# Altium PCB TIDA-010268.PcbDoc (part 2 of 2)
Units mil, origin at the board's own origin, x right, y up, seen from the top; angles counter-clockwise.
Board outline 3937.2 x 2362.29 mil, 2 copper layers (Top Layer, Bottom Layer), stack 62 mil thick; 154 components, 100 nets, 480 pads, 602 vias.
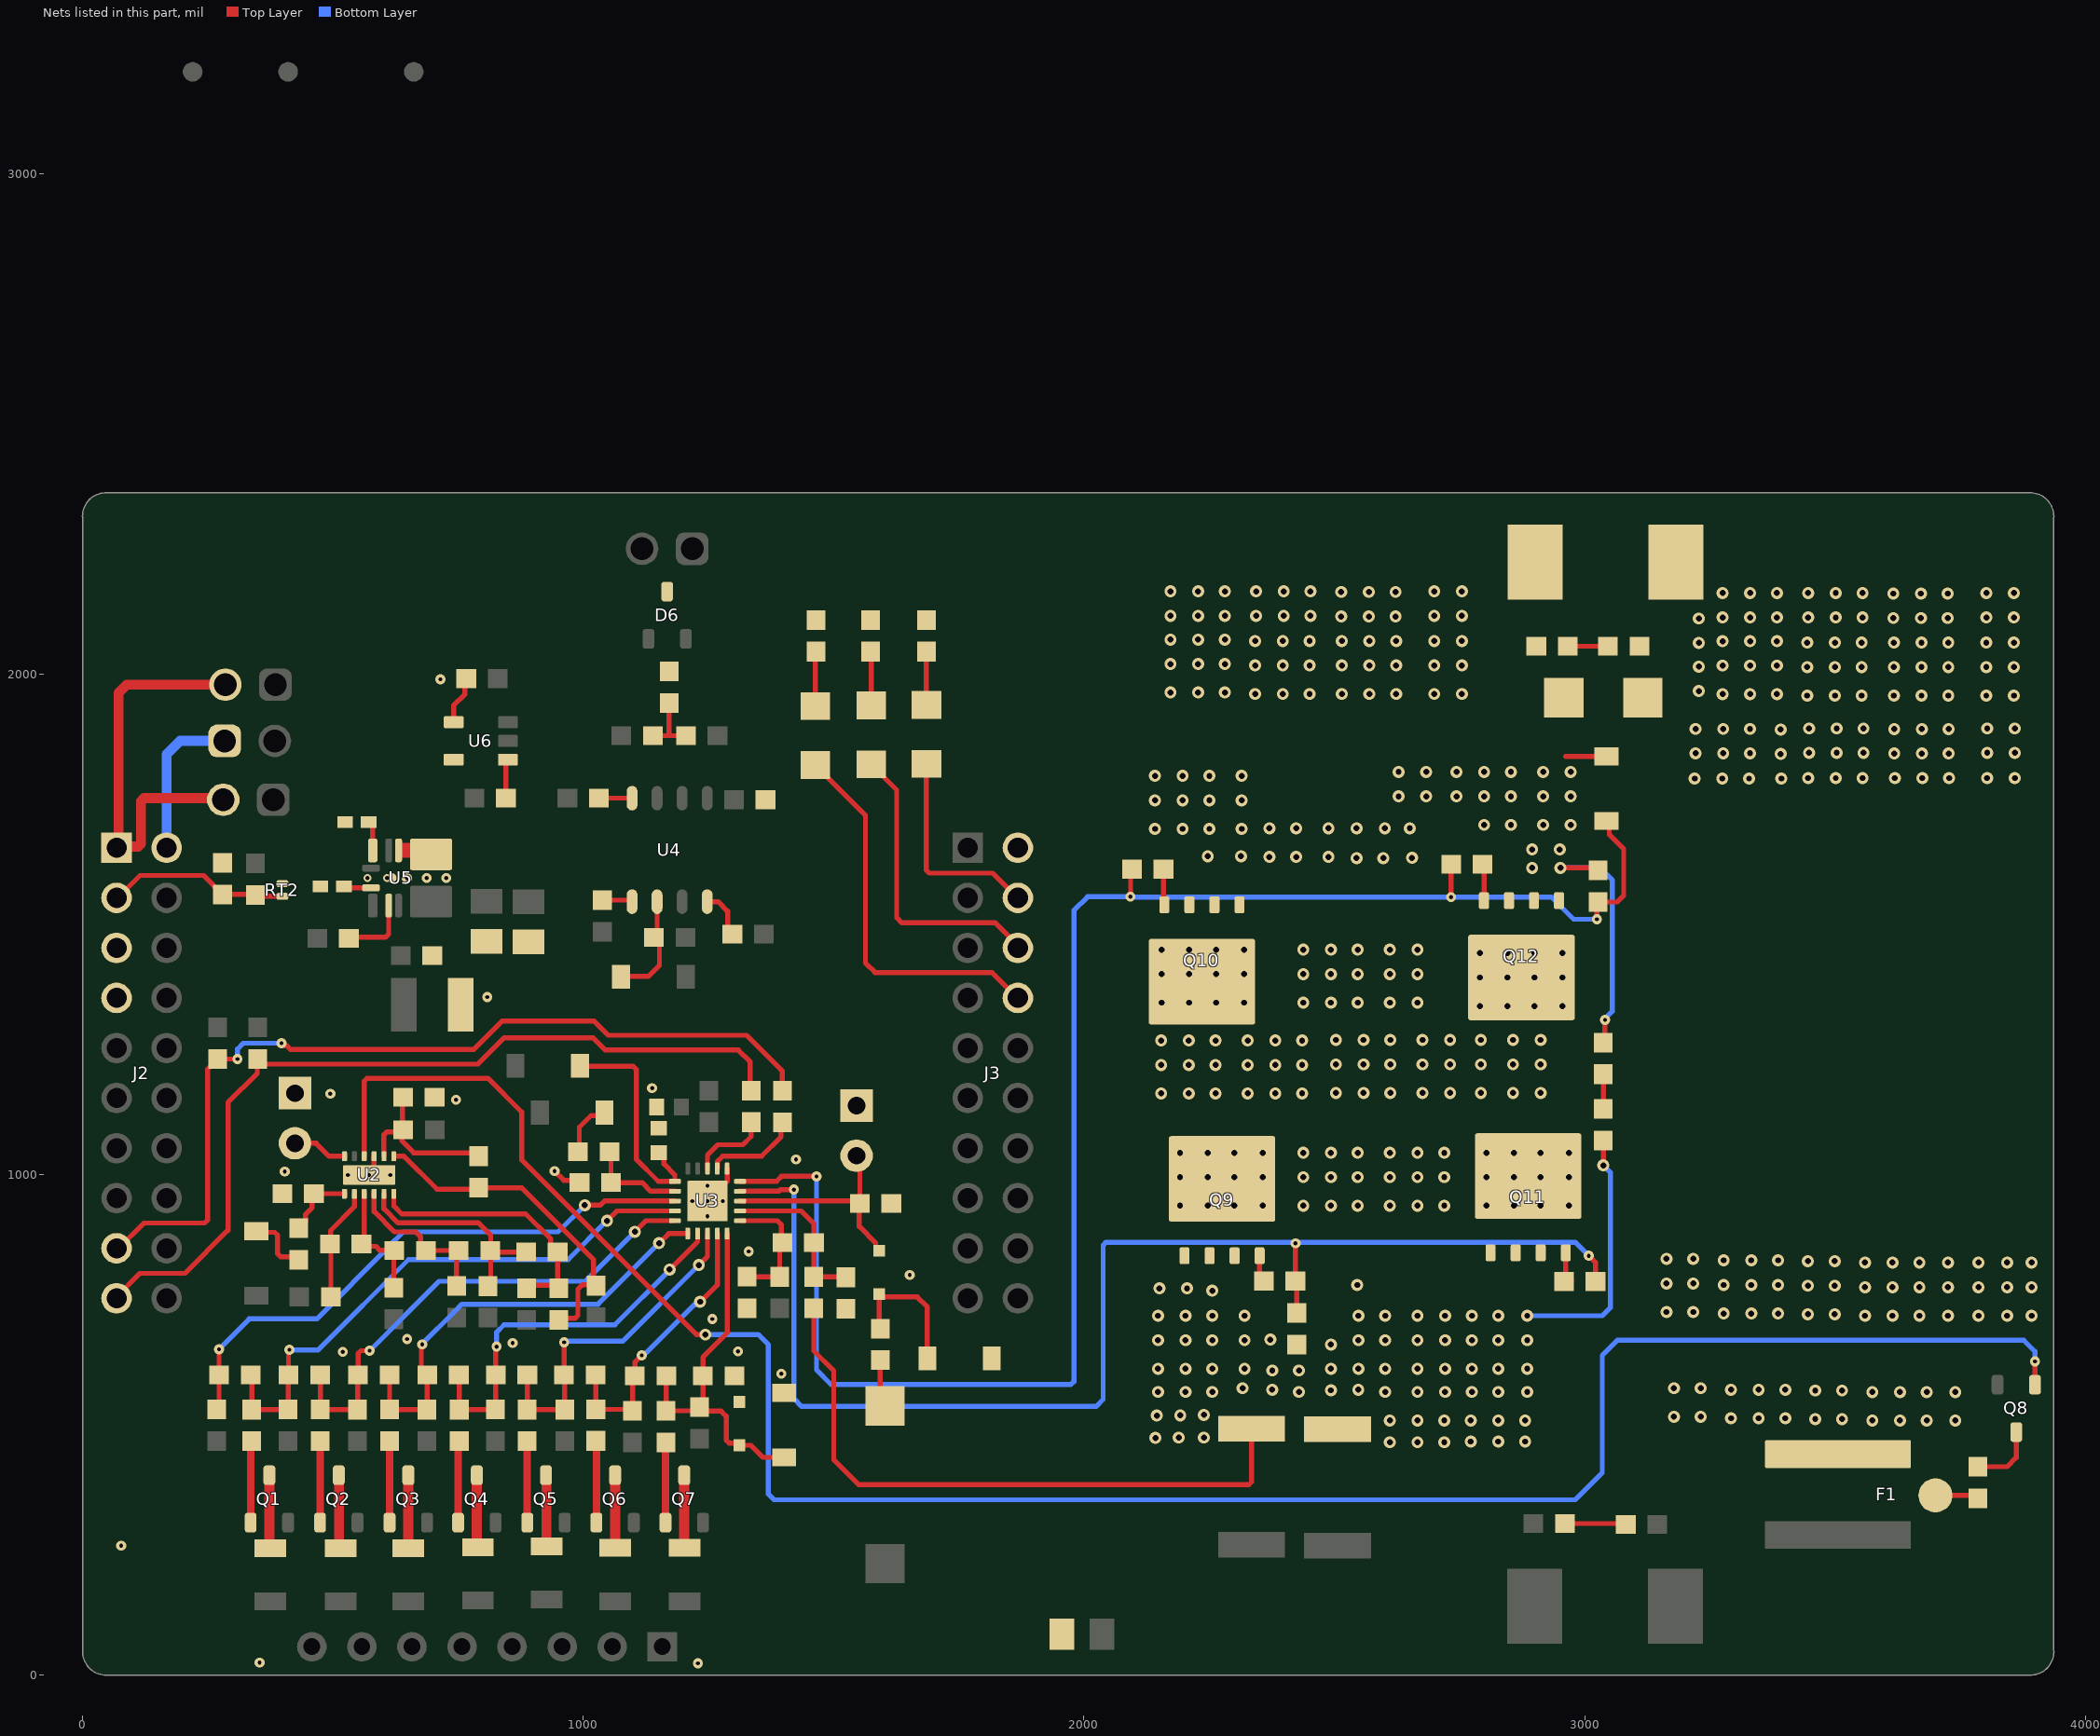
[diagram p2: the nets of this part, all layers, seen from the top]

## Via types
v1: diameter 24, hole 12, Top Layer to Bottom Layer, 526 vias
v2: diameter 20, hole 8, Top Layer to Bottom Layer, tented both sides, 55 vias
v3: diameter 19.68, hole 7.87, Top Layer to Bottom Layer, tented both sides, 8 vias
v4: diameter 19.68, hole 7.87, Top Layer to Bottom Layer, 8 vias
v5: diameter 15.75, hole 7.87, Top Layer to Bottom Layer, tented both sides, 2 vias
v6: diameter 13.78, hole 7.87, Top Layer to Bottom Layer, tented both sides, 2 vias
v7: diameter 24, hole 12, Top Layer to Bottom Layer, tented both sides, 1 vias

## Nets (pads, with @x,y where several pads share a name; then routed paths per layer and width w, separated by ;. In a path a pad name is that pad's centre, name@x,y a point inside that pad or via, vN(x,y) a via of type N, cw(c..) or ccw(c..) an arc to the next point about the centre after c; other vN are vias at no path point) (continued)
CHG: D15.1 R56.2 R60.2 R61.2 U3.10 | length 3461.5
  Top Layer w10: U3.10@1313.14,986.63 1385.98,986.63 1395.92,996.57 v2@1465.79,996.57 ; v2(2092.78,1555.22) 2093.23,1555.67 2093.23,1605.61 R60.2@2095.62,1607.99 ; v2(2733.27,1554.57) R56.2@2733.27,1619.77 ; v2(3024.25,1510.11) 3024.25,1542.15 R61.2@3026.82,1544.72 3065.2,1544.72 3078,1557.52 3078,1650.43 3049.03,1679.4 3049.03,1701.52 D15.1@3044,1706.55
  Bottom Layer w10: v2(1465.79,996.23) 1465.79,610.24 1495.16,580.87 1974.16,580.87 1980.02,586.73 1980.02,1528.03 2007.21,1555.22 v2(2092.78,1555.22) 2093.44,1554.57 v2(2733.27,1554.57) 2933.41,1554.57 2977.87,1510.11 v2(3024.25,1510.11)
COUT: Q8.1 U2.10 | length 4413.6
  Top Layer w10: U2.10@562.67,1036.66 562.67,1186.76 568.53,1192.61 809.62,1192.61 876.92,1125.32 876.92,1029.62 1225.88,680.66 1243.71,680.66 v1(1243.89,680.48) ; Q8.1@3899.4,580.24 v2(3899.4,627.01)
  Bottom Layer w10: v1(1243.89,680.48) 1349.22,680.48 1369.69,660.01 1369.69,361.82 1380.95,350.55 2981,350.55 3035.04,404.6 3035.04,639 3065.04,669 3877,669 3899.4,646.6 v2(3899.4,627.01)
DSG: R57.2 R58.2 R59.2 U3.9 | length 2634
  Top Layer w10: U3.9@1313.14,966.95 1390.87,966.95 1394.06,970.14 v2(1420.87,970.14) ; v2(2422.5,862.64) 2422.5,793.81 R59.2@2425,791.31 ; R57.2@2425,736.53 R59.2@2425,791.31 ; R59.2@2425,793.5 R59.2@2425,791.31 ; v2(3008.12,837.98) 3021.74,824.35 R58.2@3021.74,786.51
  Bottom Layer w10: v2(1420.87,970.14) 1420.87,552.59 1436.46,537 2024.19,537 2038.2,551.02 2038.2,858.96 2044.06,864.82 2422.5,864.82 2981.27,864.82 v2(3008.12,837.98)
GND: C2.1 C3.2 C14.1 C15.2 C16.1 C17.1 C18.2 C19.2 C20.2 C21.2 C22.2 C23.2 C24.2 C25.2 C26.2 C27.2 C32.1 C34.2 C39.2 C41.1 D3.2 D4.2 D5.2 D6.3 D8.2 J3.2 NT1.1 R21.1 R25.1 R26.1 R29.1 RT1.1 RT2.1 RT3.1 U2.9 U2.13 U3.11 U3.21 U4.2 U5.10 U6.1 U6.4 U6.5 | length 577.9
  Top Layer w10: v4(572.51,999.26) 582.36,1009.1 U2.9@582.36,1036.66 ; U6.4@741.22,1903.9 741.22,1937.36 763.89,1960.03 C21.2@763.89,1993.47 ; C22.2@845.55,1752.08 845.55,1825.16 U6.1@849.49,1829.1 ; v2(942.93,1006.94) 961.25,988.62 987.93,988.62 C41.1@992.57,983.98 ; D3.2@1075.65,1395.22 1074.86,1396 1129.99,1396 1152.2,1418.22 1152.2,1474.25 1147.54,1478.92 U4.2@1147.54,1545.39 ; v4(1248.18,947.26) 1287.55,986.63 U3.11@1287.55,1012.22 ; NT1.1@1954.83,83.11 NT1.1@1956.02,81.92
  other v2: 1229.24,23.8 353.49,24.99 77.39,258.87 1395.59,602.27 519.71,646.07 1308.99,646.74 859.01,663.6 648.4,671.47 1258.03,711.55 1652.14,799.6 1330.5,846.67 403.92,1006.12 1424.89,1030.57 746.03,1149.43 494.94,1161.49 1137.56,1172.94 808.17,1354.59 714.63,1989.41
  other v3: 647.77,1592.63 687.14,1592.63 726.51,1592.63
  other v4: 1248.18,916.75 1217.66,947.26 1278.69,947.26 1248.18,977.77 530.19,999.26 614.84,999.26
  other v5: 569.03,1592.63 608.4,1592.63
LED1: D9.2 J3.4 | length 436.9
  Top Layer w10: D9.2@1685.38,1839.24 1685.38,1608.3 1691.24,1602.44 1817.56,1602.44 J3.4@1868,1552
LED2: D10.2 J3.6 | length 597.8
  Top Layer w10: D10.2@1575.11,1819.31 1625.91,1768.51 1625.91,1513.59 1636.55,1502.95 1822.99,1502.95 1868,1457.94 J3.6@1868,1452
LED3: D11.2 J3.8 | length 770.5
  Top Layer w10: D11.2@1463.38,1818.24 1563.66,1717.96 1563.66,1423 1582.92,1403.74 1816.26,1403.74 J3.8@1868,1352
NetC2_2: C2.2 R6.2 U2.1 | length 142.6
  Top Layer w10: R6.2@431.84,893.04 445.54,906.74 445.54,920.99 458.57,934.02 458.57,958.46 C2.2@461.96,961.86 U2.1@523.3,961.86
NetC3_1: C3.1 J2.3 R22.1 RT2.2 | length 366.2
  Top Layer w10: J2.3@69.18,1552 114.87,1597.68 241.66,1597.68 C3.1@279.6,1559.74 344.68,1559.74 R22.1@345.55,1558.87 348.5,1555.92 RT2.2@399.19,1555.92
NetC4_1: C4.1 R34.2 U2.2 | length 226.5
  Top Layer w10: C4.1@495.59,850.78 495.59,888.42 542.99,935.82 U2.2@542.99,961.86 ; R34.2@495.96,755.77 C4.1@495.96,849.57 ; R34.2@507.08,756.8 R34.2@508.45,755.43
NetC4_2: C4.2 C5.1 R40.2 U2.3 | length 253.5
  Top Layer w10: C4.2@557.15,861.74 C4.2@562.67,861.74 ; C4.2@561.88,861.74 566.83,856.79 585.98,856.79 594.11,848.66 622.6,848.66 C5.1@622.94,848.32 621.79,847.17 R40.2@621.79,774.18 ; C4.2@562.67,855.06 C4.2@562.67,861.74 ; U2.3@562.67,961.86 C4.2@562.67,861.74
NetC5_2: C5.2 C7.1 R44.2 U2.4 | length 311.8
  Top Layer w10: U2.4@582.36,961.86 582.36,926.39 623.02,885.73 665.39,885.73 674.96,876.16 674.96,859.28 C5.2@685.93,848.32 C7.1@751.17,848.32 ; R44.2@746.67,776.92 R44.2@747.13,777.37 747.13,834.65 C7.1@752.37,839.89
NetC7_2: C7.2 C10.1 R46.2 U2.5 | length 442.2
  Top Layer w10: U2.5@602.04,961.86 602.04,931.98 630.42,903.61 790.92,903.61 808.79,885.73 815.36,879.17 C7.2@815.36,839.89 ; R46.2@809.5,777.13 815.36,782.99 C7.2@815.36,839.89 ; C10.1@885.74,845.41 882.79,845.41 820.87,845.41 C7.2@815.36,839.89
NetC10_2: C10.2 C28.1 R47.2 U2.6 | length 538.9
  Top Layer w10: U2.6@621.73,961.86 621.73,937.58 637.82,921.48 884.94,921.48 935.08,871.35 935.08,859.07 C10.2@948.73,845.41 948.73,774.91 C28.1@950.88,772.76 ; R47.2@875.94,787.45 881.64,781.74 R47.2@895.25,781.74 ; R47.2@902.24,778.01 903.54,779.31 C28.1@948.73,779.31
NetC19_1: C19.1 R35.1 R38.2 | length 131.1
  Top Layer w10: R35.1@1139.19,1877.02 1171.52,1877.02 ; C19.1@1171.52,1942.28 1171.52,1877.02 ; R38.2@1205.02,1877.02 1171.52,1877.02
NetC24_1: C24.1 U5.8 | length 59.6
  Top Layer w10: C24.1@571.62,1704 572.84,1704 579.65,1697.19 U5.8@579.65,1648.44
NetC28_2: C28.2 C38.1 R48.2 U2.7 | length 651.2
  Top Layer w10: U2.7@621.73,1036.66 642.14,1036.66 707.96,970.85 C38.1@790.97,970.85 ; C38.1@790.97,973.8 876.94,973.8 1020.69,830.04 1020.69,783.42 R48.2@1025.83,778.28 ; C28.2@964.43,715.29 964.43,712.93 964.58,712.78 983.48,712.78 989.33,718.64 989.33,771.2 997.99,779.85 1014.36,779.85 R48.2@1014.83,780.33
NetC29_2: C29.2 C31.1 | length 80
  Top Layer w10: C31.1@2966.55,2055.52 C29.2@3046.5,2055.52
NetC30_2: C30.2 C35.1 | length 122.6
  Top Layer w10: C35.1@2960.5,303 3080.11,303 C30.2@3082.24,300.87
NetC36_1: C36.1 Q9.1 Q9.2 Q9.3 Q11.1 Q11.2 Q11.3 R55.2 R57.1 R62.2 R63.2 | length 1795.4
  Top Layer w10: R55.2@1460.46,732.81 1460.46,647.9 1500.45,607.91 1500.45,430.55 1550.53,380.47 2328.87,380.47 2334.73,386.33 R62.2@2334.73,492.87 ; v1(3037.34,1018.49) C36.1@3037.34,1068.37
  Bottom Layer w10: v1(2885.26,718.08) 3035.04,718.08 3051.27,734.31 3051.27,1004.55 v1(3037.34,1018.49)
  other v1: 2611,465.5 2666.14,465.5 2719.63,465.5 2772.4,466.86 2827.54,466.86 2881.03,466.86 2142.74,474.04 2189.45,474.64 2239.58,474.64 2611,508.81 2666.14,508.81 2719.63,508.81 2772.4,508.81 2827.54,508.81 2881.03,508.81 2145.69,518.65 2192.4,519.25 2239.58,519.92 2147.83,566 2202.97,566 2256.46,566 2429.46,566 2601.76,566 2666.14,566 2721.27,566 2774.76,566 2827.54,566 2885.26,566 2493.14,569.2 2375.97,570.32 2547.85,570.32 2316.89,573.32 2376.22,608.79 2429.46,608.79 2147.83,612.27 2202.97,612.27 2256.46,612.27 2320.83,612.27 2493.14,612.27 2548.27,612.27 2601.76,612.27 2666.14,612.27 2721.27,612.27 2774.76,612.27 2827.54,612.27 2885.26,612.27 2493.14,660.59 2147.83,669.27 2202.97,669.27 2256.46,669.27 2320.83,669.27 2548.27,669.27 2601.76,669.27 2666.14,669.27 2721.27,669.27 2774.76,669.27 2827.54,669.27 2885.26,669.27 2372.18,670.43 2147.83,718.08 2202.97,718.08 2256.46,718.08 2320.83,718.08 2548.27,718.08 2601.76,718.08 2666.14,718.08 2721.27,718.08 2774.76,718.08 2827.54,718.08 2256.46,768.14 2150.68,772.91 2205.82,772.91 2545.91,779.59
NetC36_2: C36.2 C37.1 | length 69.3
  Top Layer w10: C36.2@3037.34,1131.37 C37.1@3037.34,1200.69
NetC38_2: C38.2 C39.1 R49.2 U2.8 | length 328.1
  Top Layer w10: U2.8@602.04,1036.66 602.04,1079.58 607.9,1085.44 R49.2@638.11,1085.44 ; R49.2@639.21,1089.83 C39.1@639.21,1147.4 ; R49.2@640.61,1089.83 638.11,1087.33 R49.2@638.11,1085.44 ; C38.2@790.97,1036.79 784.1,1043.66 661.59,1043.66 638.11,1067.15 R49.2@638.11,1085.44
NetC40_2: C41.2 R30.2 U3.17 | length 197.6
  Top Layer w10: R30.2@1052.35,1045.5 1055.56,1042.28 C41.2@1055.56,983.98 1117.65,983.98 1134.68,966.95 U3.17@1183.22,966.95
NetD1_1: D1.1 R6.1 | length 114.4
  Top Layer w10: D1.1@357.94,884.71 383.87,884.71 389.73,878.85 389.73,842.05 395.59,836.19 R6.1@430.72,836.19
NetD7_2: D7.2 D8.1 R43.2 | length 279.7
  Top Layer w10: D7.2@1591.04,761.17 D7.2@1591.04,755.66 ; R43.2@1595.16,690.31 1591.04,694.43 D7.2@1591.04,755.66 ; D8.1@1687.22,633.07 1687.22,735.78 1667.34,755.66 D7.2@1591.04,755.66
NetD9_1: D9.1 R25.2 | length 106.4
  Top Layer w10: D9.1@1685.38,1938.35 R25.2@1685.38,2044.8
NetD10_1: D10.1 R26.2 | length 107.9
  Top Layer w10: R26.2@1573.77,2044.8 1575.11,2043.45 D10.1@1575.11,1937.42
NetD11_1: D11.1 R29.2 | length 109.1
  Top Layer w10: D11.1@1463.38,1936.35 1463.38,2043.3 R29.2@1464.88,2044.8
NetD16_1: D16.1 R30.1 | length 112.7
  Top Layer w10: R30.1@989.35,1045.5 992.16,1048.31 992.16,1052.47 992.16,1094.65 1015.39,1117.87 1036.7,1117.87 D16.1@1042.54,1123.72
NetF1_T2: F1.T2 R45.2 | length 86.8
  Top Layer w10: F1.T2@3700.57,359.22 3779.29,359.22 R45.2@3785,353.5
NetJ2_1: J2.1 J4.2 J6.2 | length 833.4
  Top Layer w10: J2.1@68,1653 70.17,1655.17 J2.1@72.01,1657.01 ; J4.2@277.82,1752.08 J4.2@281.01,1748.9
  Top Layer w20: J2.1@70.17,1655.17 111.15,1655.17 117.01,1661.02 117.01,1746.23 122.86,1752.08 J4.2@277.82,1752.08 ; J2.1@72.01,1657.01 72.01,1962.57 88.25,1978.81 J6.2@285.26,1978.81
NetJ2_2: J2.2 J7.1 | length 313.8
  Bottom Layer w20: J2.2@168,1653 168,1839.75 194.75,1866.5 J7.1@284.01,1866.5
NetQ1_1: Q1.1 R4.1 | length 163.4
  Top Layer w10: R4.1@335.76,465.32 R4.1@337.97,467.52
  Top Layer w15: Q1.1@335.76,305.01 R4.1@335.76,465.32
NetQ1_3: Q1.3 R3.2 | length 145.9
  Top Layer w20: R3.2@373.16,253.6 Q1.3@373.16,399.49
NetQ2_1: Q2.1 R10.1 | length 162.9
  Top Layer w10: R10.1@474.45,467.34 R10.1@474.86,467.75
  Top Layer w15: Q2.1@474.45,305.01 R10.1@474.45,467.34
NetQ2_3: Q2.3 R2.2 | length 146.1
  Top Layer w10: Q2.3@511.85,399.49 Q2.3@512.26,399.09
  Top Layer w20: R2.2@512.26,253.6 Q2.3@512.26,399.09
NetQ3_1: Q3.1 R14.1 | length 162.7
  Top Layer w15: Q3.1@613.24,305.01 R14.1@613.24,467.75
NetQ3_3: Q3.3 R8.2 | length 145.9
  Top Layer w20: R8.2@650.64,253.6 Q3.3@650.64,399.49
NetQ4_1: Q4.1 R19.1 | length 163.5
  Top Layer w10: R19.1@750.12,465.18 R19.1@752.46,467.52
  Top Layer w15: Q4.1@750.12,305.01 R19.1@750.12,465.18
NetQ4_3: Q4.3 R9.2 | length 144
  Top Layer w20: R9.2@787.52,255.51 Q4.3@787.52,399.49
NetQ5_1: Q5.1 R23.1 | length 162.5
  Top Layer w15: Q5.1@888.28,305.01 R23.1@888.28,467.52
NetQ5_3: Q5.3 R12.2 | length 142.4
  Top Layer w10: Q5.3@925.68,399.49 Q5.3@926.44,398.74
  Top Layer w20: R12.2@926.44,257.43 Q5.3@926.44,398.74
NetQ6_1: Q6.1 R27.1 | length 163.6
  Top Layer w10: R27.1@1025.15,468.14 R27.1@1026.28,467.02
  Top Layer w15: Q6.1@1026.28,305.01 R27.1@1026.28,467.02
NetQ6_3: Q6.3 R13.2 | length 145.2
  Top Layer w20: R13.2@1063.68,254.28 Q6.3@1063.68,399.49
NetQ7_1: Q7.1 R31.1 | length 160.8
  Top Layer w10: R31.1@1164.28,463.9 R31.1@1165.62,465.25
  Top Layer w15: Q7.1@1164.28,305.01 R31.1@1164.28,463.9
NetQ7_3: Q7.3 R17.2 | length 145.2
  Top Layer w20: R17.2@1201.68,254.28 Q7.3@1201.68,399.49
NetQ8_3: Q8.3 R45.1 | length 135.5
  Top Layer w10: R45.1@3785,416.5 3843.68,416.5 3862,434.82 Q8.3@3862,485.76
NetQ9_4: Q9.4 R59.1 | length 55.6
  Top Layer w10: Q9.4@2350.82,837.98 2350.82,786.51 R59.1@2353.78,783.56
NetQ9_5: Q9.5 Q9.6 Q9.7 Q9.8 Q9.9@2275.82,991.52 Q10.5 Q10.6 Q10.7 Q10.8 Q10.9@2235.64,1385.43 Q11.5 Q11.6 Q11.7 Q11.8 Q11.9@2887.13,997.21 Q12.5 Q12.6 Q12.7 Q12.8 Q12.9@2873.8,1393.86
  other v1: 2191.91,938 2247.05,938 2300.54,938 2357,938 2438,938 2493.14,938 2546.63,938 2611,938 2666.14,938 2719.63,938 2803.51,938 2858.64,938 2912.13,938 2968.59,938 2191.91,995 2247.05,995 2300.54,995 2357,995 2438,995 2493.14,995 2546.63,995 2611,995 2666.14,995 2719.63,995 2803.51,995 2858.64,995 2912.13,995 2968.59,995 2191.91,1043.82 2247.05,1043.82 2300.54,1043.82 2357,1043.82 2438,1043.82 2493.14,1043.82 2546.63,1043.82 2611,1043.82 2666.14,1043.82 2719.63,1043.82 2803.51,1043.82 2858.64,1043.82 2912.13,1043.82 2968.59,1043.82 2154.16,1162.14 2209.29,1162.14 2262.78,1162.14 2327.16,1162.14 2382.29,1162.14 2435.78,1162.14 2503.18,1163.27 2558.32,1163.27 2611.81,1163.27 2676.18,1163.27 2731.32,1163.27 2792.63,1163.27 2857,1163.27 2912.13,1163.27 2154.16,1219.14 2209.29,1219.14 2262.78,1219.14 2327.16,1219.14 2382.29,1219.14 2435.78,1219.14 2503.18,1220.27 2558.32,1220.27 2611.81,1220.27 2676.18,1220.27 2731.32,1220.27 2792.63,1220.27 2857,1220.27 2912.13,1220.27 2154.16,1267.96 2209.29,1267.96 2262.78,1267.96 2327.16,1267.96 2382.29,1267.96 2435.78,1267.96 2503.18,1269.09 2558.32,1269.09 2611.81,1269.09 2676.18,1269.09 2731.32,1269.09 2792.63,1269.09 2857,1269.09 2912.13,1269.09 2790.71,1336.89 2845.85,1336.89 2899.34,1336.89 2955.8,1336.89 2155.07,1343.54 2210.21,1343.54 2263.7,1343.54 2320.16,1343.54 2438,1343.54 2493.14,1343.54 2546.63,1343.54 2611,1343.54 2666.14,1343.54 2790.71,1393.89 2845.85,1393.89 2899.34,1393.89 2955.8,1393.89 2155.07,1400.54 2210.21,1400.54 2263.7,1400.54 2320.16,1400.54 2438,1400.54 2493.14,1400.54 2546.63,1400.54 2611,1400.54 2666.14,1400.54 2790.71,1442.71 2845.85,1442.71 2899.34,1442.71 2955.8,1442.71 2155.07,1449.36 2210.21,1449.36 2263.7,1449.36 2320.16,1449.36 2438,1449.36 2493.14,1449.36 2546.63,1449.36 2611,1449.36 2666.14,1449.36
NetQ10_4: Q10.4 R60.1 | length 72
  Top Layer w10: R60.1@2158.72,1610.22 2158.72,1540.89 Q10.4@2160.64,1538.97
NetQ11_4: Q11.4 R58.1 | length 59.3
  Top Layer w10: Q11.4@2962.13,843.67 2962.13,800.42 R58.1@2973.52,789.03
NetQ12_4: Q12.4 R56.1 | length 72.4
  Top Layer w10: Q12.4@2799.48,1547.4 R56.1@2799.48,1619.77
NetR18_2: R18.2 U5.2 | length 136.1
  Top Layer w10: R18.2@534.96,1474.25 605.01,1474.25 611.55,1480.79 U5.2@611.55,1537.51 ; U5.2@611.54,1538.12 U5.2@611.62,1538.2
NetR21_2: R21.2 U5.11 | length 56.1
  Top Layer w10: R21.2@522.41,1577.34 526.8,1572.95 U5.11@576.12,1572.95 ; U5.11@575.8,1573.26 U5.11@576.18,1573.64
NetR32_1: R32.1 U3.12 | length 191.4
  Top Layer w10: U3.12@1267.86,1012.22 1267.86,1026.12 1278.65,1036.91 1356.23,1036.91 1394.9,1075.58 1394.9,1101.62 R32.1@1397.69,1104.41
NetR36_1: R36.1 U3.13 | length 159.2
  Top Layer w10: U3.13@1248.18,1012.22 1248.18,1039.27 1268.53,1059.62 1318.67,1059.62 1335.09,1076.04 1335.09,1105.57 R36.1@1335.43,1105.91
NetR37_2: R37.2 U4.1 | length 60.6
  Top Layer w10: R37.2@1038.18,1548.38 1094.55,1548.38 U4.1@1097.54,1545.39
NetR39_2: R39.2 U4.8 | length 66
  Top Layer w10: R39.2@1031.54,1752.08 U4.8@1097.54,1752.08
NetR42_2: R42.2 U4.4 | length 102.7
  Top Layer w10: U4.4@1247.54,1545.39 1269.35,1545.39 1288.33,1526.41 1288.33,1473.66 R42.2@1289.28,1472.72
NetR43_1: R43.1 S1.1 | length 98.4
  Top Layer w10: R43.1@1593.1,623.23 1593.1,562.23 S1.1@1619.55,535.78
NetRT1_2: RT1.2 U2.12 | length 109.8
  Top Layer w10: RT1.2@424.25,1062.67 466.56,1062.67 492.57,1036.66 U2.12@523.3,1036.66
NetU5_5: U5.5 U5.6 | length 59.9
  Top Layer w10: U5.5@688.32,1647.75 U5.5@696.19,1639.88
  Top Layer w30: 639.59,1647.75 U5.5@688.32,1647.75
PACK+: C29.1 D12.2 D13.1 F1.T3
  other v1: 3574.54,508.81 3629.67,508.81 3683.17,508.81 3740.25,508.81 3460.5,511.81 3513.99,511.81 3292.26,513.32 3347.4,513.32 3400.89,513.32 3178.22,516.32 3231.71,516.32 3574.54,565.81 3629.67,565.81 3683.17,565.81 3740.25,565.81 3460.5,568.81 3513.99,568.81 3292.26,570.32 3347.4,570.32 3400.89,570.32 3178.22,573.32 3231.71,573.32 3559.81,718.08 3614.95,718.08 3668.44,718.08 3725.53,718.08 3786.59,718.08 3843.68,718.08 3892.66,718.08 3445.77,721.08 3499.26,721.08 3277.54,722.59 3332.67,722.59 3386.16,722.59 3163.5,725.59 3216.99,725.59 3559.81,775.08 3614.95,775.08 3668.44,775.08 3725.53,775.08 3786.59,775.08 3843.68,775.08 3892.66,775.08 3445.77,778.08 3499.26,778.08 3277.54,779.59 3332.67,779.59 3386.16,779.59 3163.5,782.59 3216.99,782.59 3559.81,824.35 3614.95,824.35 3668.44,824.35 3725.53,824.35 3786.59,824.35 3843.68,824.35 3892.66,824.35 3445.77,827.35 3499.26,827.35 3277.54,828.85 3332.67,828.85 3386.16,828.85 3163.5,831.86 3216.99,831.86 3219.75,1791.28 3274.88,1791.28 3328.37,1791.28 3392.75,1791.28 3446.37,1792.18 3501.5,1792.18 3555,1792.18 3619.37,1792.18 3674.5,1792.18 3728,1792.18 3803.91,1792.18 3859.04,1792.18 3391.57,1840.47 3618.19,1841.37 3673.33,1841.37 3726.82,1841.37 3221.57,1841.68 3276.7,1841.68 3330.19,1841.68 3448.19,1842.58 3503.32,1842.58 3556.81,1842.58 3803.99,1842.58 3859.12,1842.58 3391.57,1889.28 3221.57,1890.49 3276.7,1890.49 3330.19,1890.49 3618.19,1890.19 3673.33,1890.19 3726.82,1890.19 3448.19,1891.4 3503.32,1891.4 3556.81,1891.4 3803.99,1891.4 3859.12,1891.4 3444.55,1956.97 3499.69,1956.97 3553.18,1956.97 3617.55,1956.97 3672.69,1956.97 3726.18,1956.97 3802.09,1956.97 3857.22,1956.97 3275.37,1959.98 3330.51,1959.98 3384,1959.98 3228,1966 3444.55,2013.97 3499.69,2013.97 3553.18,2013.97 3617.55,2013.97 3672.69,2013.97 3726.18,2013.97 3802.09,2013.97 3857.22,2013.97 3228,2014.82 3275.37,2016.98 3330.51,2016.98 3384,2016.98 3228,2062.21 3444.55,2062.79 3499.69,2062.79 3553.18,2062.79 3617.55,2062.79 3672.69,2062.79 3726.18,2062.79 3802.09,2062.79 3857.22,2062.79 3275.37,2065.79 3330.51,2065.79 3384,2065.79 3228,2111.02 3616.37,2111.98 3671.51,2111.98 3725,2111.98 3275.37,2113.18 3330.51,2113.18 3384,2113.18 3446.37,2113.18 3501.5,2113.18 3555,2113.18 3802.17,2113.18 3857.3,2113.18 3616.37,2160.79 3671.51,2160.79 3725,2160.79 3275.37,2162 3330.51,2162 3384,2162 3446.37,2162 3501.5,2162 3555,2162 3802.17,2162 3857.3,2162
PACK-: C31.2 C37.2 D12.1 D13.2 D15.2 Q10.1 Q10.2 Q10.3 Q12.1 Q12.2 Q12.3 R61.1 | length 599.7
  Top Layer w10: v1(2951.75,1612.86) 3021.67,1612.86 R61.1@3026.82,1607.72 ; 2962.24,1835.49 D15.2@3043.55,1835.49 ; C37.2@3037.34,1263.68 3040.59,1266.94 v2(3040.59,1309.01)
  Bottom Layer w10: v1(2951.75,1612.86) 3030.53,1612.86 3055.36,1588.03 3055.36,1326.49 v2@3041.87,1313
  other v1: 2895.12,1612.86 2544.51,1632.38 2598,1632.38 2655.08,1632.87 2370.51,1634.77 2424,1634.77 2488.37,1634.77 2247.33,1636.07 2313.58,1636.07 2895.12,1649.5 2950.26,1649.5 2141.89,1690.81 2197.02,1690.81 2250.51,1690.81 2314.89,1690.81 2370.51,1691.77 2424,1691.77 2488.37,1691.77 2544.51,1691.77 2600.94,1691.77 2650.76,1691.77 2799.21,1698.6 2852.7,1698.6 2917.07,1698.6 2972.21,1698.6 2141.89,1747.81 2197.02,1747.81 2250.51,1747.81 2314.89,1747.81 2628.37,1755.6 2683.5,1755.6 2744.07,1755.6 2799.21,1755.6 2852.7,1755.6 2917.07,1755.6 2972.21,1755.6 2141.89,1796.62 2197.02,1796.62 2250.51,1796.62 2314.89,1796.62 2628.37,1804.41 2683.5,1804.41 2744.07,1804.41 2799.21,1804.41 2852.7,1804.41 2917.07,1804.41 2972.21,1804.41 2342,1960.13 2397.13,1960.13 2450.63,1960.13 2515,1960.13 2570.13,1960.13 2623.63,1960.13 2699.54,1960.13 2754.67,1960.13 2172.82,1963.13 2227.96,1963.13 2281.45,1963.13 2342,2017.13 2397.13,2017.13 2450.63,2017.13 2515,2017.13 2570.13,2017.13 2623.63,2017.13 2699.54,2017.13 2754.67,2017.13 2172.82,2020.13 2227.96,2020.13 2281.45,2020.13 2342,2065.94 2397.13,2065.94 2450.63,2065.94 2515,2065.94 2570.13,2065.94 2623.63,2065.94 2699.54,2065.94 2754.67,2065.94 2172.82,2068.95 2227.96,2068.95 2281.45,2068.95 2513.82,2115.13 2568.96,2115.13 2622.45,2115.13 2172.82,2116.34 2227.96,2116.34 2281.45,2116.34 2343.82,2116.34 2398.95,2116.34 2452.44,2116.34 2699.62,2116.34 2754.75,2116.34 2513.82,2163.95 2568.96,2163.95 2622.45,2163.95 2172.82,2165.16 2227.96,2165.16 2281.45,2165.16 2343.82,2165.16 2398.95,2165.16 2452.44,2165.16 2699.62,2165.16 2754.75,2165.16
REGSRC: C15.1 D2.1 U3.16 | length 469
  Top Layer w10: D2.1@984.56,1216.37 1100.07,1216.37 1105.92,1210.52 1105.92,1030.57 1149.87,986.63 U3.16@1183.22,986.63 ; C15.1@1151.39,1043.66 1161.16,1033.9 1161.16,1021.29 1182.94,999.51 U3.16@1182.94,986.91
RX_URAT: J2.5
SCL: J2.17 R15.1 R32.2 | length 1794.8
  Top Layer w10: J2.17@70.22,850.97 122.57,903.32 243.81,903.32 249.66,909.18 249.66,1210.52 255.52,1216.37 256.12,1216.37 269.82,1230.08 R15.1@269.82,1231.06 ; R15.1@271,1230.27 271.79,1231.06 v2(309.43,1231.06) ; v2(397.48,1262.56) 400.19,1262.56 405.19,1257.56 407.57,1257.56 415.02,1250.1 781.58,1250.1 837.99,1306.51 1022.03,1306.51 1050.13,1278.42 1325.88,1278.42 1397.69,1206.61 R32.2@1397.69,1167.4
  Bottom Layer w10: v2(309.43,1231.06) 309.43,1250.67 321.31,1262.56 v2(397.48,1262.56)
SDA: J2.19 R5.1 R36.2 | length 1734.4
  Top Layer w10: J2.19@66.56,754.62 114.84,802.9 204.7,802.9 290.77,888.98 290.77,1144.1 348.91,1202.23 348.91,1230.11 358.18,1220.84 789.49,1220.84 842.26,1273.61 1019.34,1273.61 1043.97,1248.98 1309.7,1248.98 1333.48,1225.2 R36.2@1333.48,1166.22
SRN: C33.2 C34.1 R55.1 U3.7 | length 315.7
  Top Layer w10: U3.7@1313.14,927.58 1435.01,927.58 1460.51,902.07 C33.2@1460.51,875.75 ; C33.2@1458.72,864.29 1460.46,862.55 R55.1@1460.46,795.8 C34.1@1522.71,795.8
SRP: C32.2 C33.1 R54.2 U3.6 | length 254.4
  Top Layer w10: U3.6@1313.14,907.89 1387.65,907.89 1395.73,899.82 1395.73,864.29 1392.46,861.03 R54.2@1392.46,795.8 C32.2@1329.41,795.8
TS: C27.1 D7.1 RT3.2 U3.8 | length 453.5
  Top Layer w10: U3.8@1313.14,947.26 C27.1@1547.6,947.26 ; C27.1@1545.86,949 C27.1@1552.39,942.47 ; RT3.2@1545.86,1037.95 1552.39,1031.42 C27.1@1552.39,942.47 ; D7.1@1591.04,847.78 1584.23,854.6 1584.23,863.57 1551.25,896.55 1551.25,941.33 C27.1@1552.39,942.47
TX_URAT: J2.7
VC0: C13.2 C18.1 D4.1 D5.1 R31.2 R33.2 U3.5 | length 746.5
  Top Layer w10: C13.2@1166.18,597.75 1165.62,597.19 R31.2@1165.62,528.24 1238.4,528.24 R33.2@1239.08,527.56 ; U3.5@1287.55,882.3 1287.55,683.72 1239.08,635.25 C18.1@1239.08,597.75 R33.2@1239.08,527.56 ; D4.1@1401.18,435.26 1359.19,435.26 1334.96,459.49 D5.1@1312.15,459.49 1307.91,463.73 1291.55,463.73 1285.69,469.58 1285.69,517.24 1275.37,527.56 R33.2@1239.08,527.56
VC1: C12.2 C13.1 R27.2 R28.2 U3.4 | length 573.4
  Top Layer w10: C12.2@1024.72,599.57 1025.15,599.14 R27.2@1025.15,531.13 1095.69,531.13 R28.2@1098.57,528.24 1098.57,593.14 1103.5,598.06 1103.5,625.59 v2(1116.86,638.95) ; v1(1233.3,746.07) 1234.22,746.07 1267.86,779.71 U3.4@1267.86,882.3
  Bottom Layer w10: v2(1116.86,638.95) 1119.56,638.95 1124.56,643.95 1125.28,643.95 1221.25,739.93 1223.37,739.93 1229.51,746.07 v1(1233.3,746.07)
VC2: C11.2 C12.1 R23.2 R24.2 U3.3 | length 682.1
  Top Layer w10: C11.2@888.28,599.57 R23.2@888.28,530.52 R24.2@963.08,530.52 963.08,598.22 C12.1@961.73,599.57 v2(961.73,664.94) ; v1(1230.9,819.28) 1248.18,836.56 U3.3@1248.18,882.3
  Bottom Layer w10: v2(961.73,664.94) 963.9,667.11 1078.73,667.11 v1(1230.9,819.28)
VC3: C9.2 C11.1 R19.2 R20.2 U3.2 | length 790.4
  Top Layer w10: C9.2@751.54,599.57 752.46,598.65 R19.2@752.46,530.52 824.69,530.52 R20.2@824.92,530.74 824.92,599.21 C11.1@825.28,599.57 825.28,654.64 v2(827.13,656.48) ; v1(1172.53,810.39) 1228.49,866.35 U3.2@1228.49,882.3
  Bottom Layer w10: v2(827.13,656.48) 827.13,685.26 841.87,700 1063.27,700 1172.53,809.26 v1(1172.53,810.39)
VC4: C8.2 C9.1 R14.2 R16.2 U3.1 | length 902.1
  Top Layer w10: C8.2@613.24,599.57 R14.2@613.24,530.75 613.46,530.52 R16.2@688.04,530.52 C9.1@688.04,599.06 ; v2(678.48,660.68) 676.65,658.86 676.65,611.46 C9.1@688.55,599.57 ; v1(1151.39,863.1) 1170.6,882.3 U3.1@1208.81,882.3
  Bottom Layer w10: v2(678.48,660.68) 678.48,662.16 742.23,725.91 757.58,741.26 1029.56,741.26 v1(1151.39,863.1)
VC5: C6.2 C8.1 R10.2 R11.2 U3.20 | length 998.7
  Top Layer w10: C6.2@474.45,599.57 474.86,599.16 R10.2@474.86,530.75 475.09,530.52 R11.2@549.25,530.52 549.25,598.58 C8.1@550.24,599.57 550.24,642.34 556.1,648.2 v2(573.26,648.2) v2@573.77,648.71 ; v1(1103.19,886.02) 1125.06,907.89 U3.20@1183.22,907.89
  Bottom Layer w10: v2@573.77,648.71 712.05,786.99 1004.16,786.99 v1(1103.19,886.02)
VC6: C1.2 C6.1 R4.2 R7.2 U3.19 | length 1148
  Top Layer w10: C1.2@335.76,599.57 337.97,597.36 R4.2@337.97,530.52 410.34,530.52 R7.2@410.57,530.75 410.57,598.68 C6.1@411.46,599.57 411.46,648.22 v2(413.29,650.05) ; v1(1047.47,907.68) 1067.37,927.58 U3.19@1183.22,927.58
  Bottom Layer w10: v2(413.29,650.05) 470.77,650.05 650.98,830.26 970.06,830.26 v1(1047.47,907.68)
VC7: C1.1 R1.2 U3.18 | length 1156.6
  Top Layer w10: R1.2@268.31,530.75 272.77,535.2 v2(272.77,651.18) v2@272.45,651.5 ; v1(1003.13,939.07) 1023.37,939.07 1034.1,939.07 1042.3,947.26 U3.18@1183.22,947.26
  Bottom Layer w10: v2@272.45,651.5 332.85,711.9 467.9,711.9 610.74,854.74 610.74,855.71 640.76,885.73 949.8,885.73 v1(1003.13,939.07)
pads on no net: FID1.1 FID2.1 FID3.1 J2.4 J2.6 J2.8 J2.10 J2.11 J2.12 J2.13 J2.14 J2.15 J2.16 J2.18 J2.20 J3.1 J3.3 J3.5 J3.9 J3.10 J3.11 J3.13 J3.14 J3.15 J3.16 J3.18 J3.20 LBL1.0 Q9.9@2182.42,916.32 Q9.9@2223.46,927.94 Q9.9@2223.46,973.21 Q9.9@2223.46,1018.49 Q9.9@2275.82,927.94 Q9.9@2275.82,973.21 Q9.9@2275.82,978.53 Q9.9@2275.82,1018.49 Q9.9@2328.19,927.94 Q9.9@2328.19,973.21 Q9.9@2328.19,1018.49 Q9.9@2369.23,916.32 Q10.9@2142.23,1460.63 Q10.9@2183.28,1358.46 Q10.9@2183.28,1403.74 Q10.9@2183.28,1449.01 Q10.9@2235.64,1358.46 Q10.9@2235.64,1398.42 Q10.9@2235.64,1403.74 Q10.9@2235.64,1449.01 Q10.9@2288,1358.46 Q10.9@2288,1403.74 Q10.9@2288,1449.01 Q10.9@2329.04,1460.63 Q11.9@2793.73,922.01 Q11.9@2834.77,933.63 Q11.9@2834.77,978.9 Q11.9@2834.77,1024.18 Q11.9@2887.13,933.63 Q11.9@2887.13,978.9 Q11.9@2887.13,984.22 Q11.9@2887.13,1024.18 Q11.9@2939.5,933.63 Q11.9@2939.5,978.9 Q11.9@2939.5,1024.18 Q11.9@2980.54,922.01 Q12.9@2780.4,1469.06 Q12.9@2821.44,1366.89 Q12.9@2821.44,1412.17 Q12.9@2821.44,1457.44 Q12.9@2873.8,1366.89 Q12.9@2873.8,1406.85 Q12.9@2873.8,1412.17 Q12.9@2873.8,1457.44 Q12.9@2926.16,1366.89 Q12.9@2926.16,1412.17 Q12.9@2926.16,1457.44 Q12.9@2967.21,1469.06 RT2.1S RT2.2S U2.11 U5.1 U5.7

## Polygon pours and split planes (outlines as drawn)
GND on Top Layer "Top Layer-GND" (solid, remove dead copper, pour order 35): 1927.97,37.25 1938.62,47.9 1938.94,47.58 1990.05,47.58 1990.05,109.4 1941.69,109.4 1927.97,123.12 1927.97,2343.04 1906.21,2358.69 47.69,2362.2 8.99,2321.75 9,39.29 45.6,-3.43 1916.59,-3.43 1927.97,11
PACK- on Top Layer "TOP_LAYER_PACK-_P036" (solid, pour order 36): 2839.81,1518.38 2839.81,1662.82 2828.67,1676.37 2690.28,1676.37 2676.73,1662.82 2676.73,1518.38 2203.92,1518.38 2203.92,1651.19 2196.23,1666.02 2120,1666.02 2120,2335.1 2131.16,2352.2 2949.05,2352.2 2957.66,2337.69 2957.66,2097.54 2928.99,2097.54 2924.99,2094.82 2925.02,2004.14 2927.52,1997.53 2996.08,1997.53 2996.08,1524.5 2989.95,1518.38
NetQ9_5 on Top Layer "Top Layer-NetQ9_5" (solid, pour order 14): 2117,902 2130,889 2981.2,887.51 2992.37,894.69 2992.09,1081.07 2992.37,1359.47 2992.44,1429.68 2992.47,1464.85 2988.17,1480 2912.35,1481.17 2483.67,1481.17 2438,1481.17 2395.61,1481.17 2291.3,1480 2131.62,1482.12 2117,1468.41
NetC36_1 on Top Layer "Top Layer-NetC36_1" (solid, pour order 12): 2127.23,865.18 2119.67,856.52 2119.67,429.44 2133.3,413.37 2968.29,412.77 2991.48,432.97 2993.18,723.08 2988.33,728.67 2931.9,728.67 2925.79,740.16 2924.3,861.28 2493.28,861.28 2483.46,851.46 2483.46,763.98 2481.47,759.31 2455.06,759.31 2454.29,692.47 2395.68,691.71 2395.83,757.11 2321.8,757.11 2314.95,763.98 2315.36,864.82
PACK+ on Top Layer "TOP_LAYER_PACK+_P025" (solid, pour order 25): 3089.22,2002.74 3075.73,1988.39 3074.58,1909.85 3136.49,1910.31 3147,1902.09 3147,424.82 3159.81,413.07 3650.19,413.99 3770.33,466.66 3770.52,642.13 3779.29,651.67 3937.01,651.67 3937.01,2325.56 3877.23,2362.21 3109.19,2362.29 3089.95,2343.05
BAT- on Top Layer "TOP_LAYER_BAT-_P017" (solid, pour order 17): 2120,302.26 2139.82,315.51 2862.13,316.23 2862.13,325.7 2867.98,331.54 2921,331.54 2921,260.46 2927.72,253.93 2976.62,254.5 2976.62,0 2976.62,17.04 2970.73,0 2136.92,0.01 2120,18.62
BAT- on Top Layer "TOP_LAYER_BAT-_P033" (solid, pour order 33): 2010.98,112.83 2011.04,112.77 2117.75,112.77 2123.29,118.32 2133.77,118.32 2133.77,44.78 2118.55,44.78 2112.32,51.01 2010.98,51.01
BAT+ on Top Layer "TOP_LAYER_BAT+_P026" (solid, pour order 26): 3123,329.41 3123,20.27 3131.03,0 3900.54,0 3937.01,27.61 3937.01,305.68 3919,321.8
GND on Bottom Layer "BOTTOM_LAYER_GND_P027" (solid, pour order 27): 0,2317.81 47.69,2362.2 1901.42,2362.2 1927.97,2342.99 1927.97,11 1919.3,0 42.83,0 0,49.99
PACK- on Bottom Layer "BOTTOM_LAYER_PACK-_P016" (solid, pour order 16): 2996.1,1585.1 2120,1585.1 2120,2344.85 2131.16,2362.2 2949.05,2362.2 2957.66,2347.69 2957.66,2107.54 2929.1,2107.54 2924.99,2104.82 2924.92,2014.41 2927.52,2007.53 2985.55,2007.53 2996.29,1999.1
NetQ9_5 on Bottom Layer "BOTTOM_LAYER_NETQ9_5_P022" (solid, pour order 22): 2117,1468.41 2130.78,1482.19 2981.26,1482.04 2992.37,1470.25 2992.37,894.69 2986.68,889 2129.58,889.06 2117,902
BAT- on Bottom Layer "BOTTOM_LAYER_BAT-_P024" (solid, pour order 24): 2120,302.48 2141.16,316.19 2961.63,315.56 2976.68,300.5 2975.99,15.53 2970.73,0 2136.45,0.57 2120,18.63
NetC36_1 on Bottom Layer "BOTTOM_LAYER_NETC36_1_P023" (solid, pour order 23): 2119.5,791.31 2141.6,800.15 2985.63,800.42 2992.13,795.6 2992.25,433.74 2968.65,412.99 2133.26,413.15 2119.5,429.9
PACK+ on Bottom Layer "BOTTOM_LAYER_PACK+_P019" (solid, pour order 19): 3090.21,2003.73 3077.99,1995.79 3077.99,1909.88 3137.15,1909.88 3147,1902.09 3147,424.82 3159.54,413.35 3654.78,416 3770.33,466.52 3770.33,687.66 3919,687.66 3937.01,698.23 3936.31,2323.36 3881.05,2362.2 3110.66,2362.2 3089.62,2342.75
BAT+ on Bottom Layer "BOTTOM_LAYER_BAT+_P020" (solid, pour order 20): 3126.57,329.63 3123,324.65 3123,20.04 3130.71,0 3902.32,0 3937.01,28.32 3935.25,307.19 3919,321.8

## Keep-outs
Keep-Out Layer:
  text ".Layer_Name" at 577,-858.49 h60

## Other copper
Top Layer:
  text ".Layer_Name" at 577,-858.49 h60
Bottom Layer:
  text ".Layer_Name" at 577,-858.49 h60

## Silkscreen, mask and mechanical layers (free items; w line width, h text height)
Top Overlay:
  lines w10: 1259.97,428.04 1259.97,414.99 1521.11,153.85 ; 1832.61,49.19 1326.22,49.19 1326.22,134.66 1832.61,134.66 1832.61,51.09
  text "PACK-" at 2747.48,2315 h30
  text "PACK+" at 3189,2315 h30
  text "'.PRJ_Number'A" at 86.51,2091 h50
  text "2023.11.23  Rev C" at 33.98,27.41 h30
  text "BAT+" at 3220.67,19.61 h30
  text "BAT-" at 2699,19 h30
  text "cell0" at 1258.3,16 h20 r90
  text "cell7" at 387.36,15.2 h20 r90
  text ".Layer_Name" at 577,-858.49 h60
Bottom Overlay:
  text ".Layer_Name" at 577,-858.49 h60
Top Paste:
  text ".Layer_Name" at 577,-858.49 h60
Bottom Paste:
  text ".Layer_Name" at 577,-858.49 h60
Top Solder:
  region: 2676,11 2676,152 2149,152 2149,11
  region: 3876.9,2195.72 3876.9,2336.72 3349.9,2336.72 3349.9,2195.72
  region: 2726,2201 2726,2342 2199,2342 2199,2201
  region: 3872.57,13 3872.57,154 3345.57,154 3345.57,13
  text ".Layer_Name" at 577,-858.49 h60
  text ".Layer_Name" at 577,-858.49 h60
Bottom Solder:
  text ".Layer_Name" at 577,-858.49 h60
Drill Guide:
  text ".Layer_Name" at 577,-858.49 h60
M1 Board Outline:
  lines w10: -0.09,2315.12 cw(c47.3,2314.91) 47.84,2362.29 ; 0,2314.52 0.09,47.99 ccw(c47.48,47.45) 47.27,0.06 ; 47.27,0 3887.97,0 ; 47.69,2362.2 3887.56,2362.2 ; 3889.19,0.01 ccw(c3889.73,47.39) 3937.11,47.19 ; 3889.92,2362.29 cw(c3889.71,2314.91) 3937.09,2314.37 ; 3937.01,49.03 3937.01,2312.76
  text ".Layer_Name" at 577,-858.49 h60
M2 Board Dimensions:
  rectangle: 0,-275 125,-150
  rectangle: 125,-400 500,-275
  lines w7: 0,-275 1000,-275 ; 125,-400 125,-150 ; 250,-400 250,-150 ; 500,-400 500,-150 ; 750,-400 750,-150 ; 0,-400 1000,-400 1000,-150 0,-150 0,-400
  text ".Layer_Name" at 577,-858.49 h60
M3 3D STEP Top:
  text ".Layer_Name" at 577,-858.49 h60
M4 3D STEP Bottom:
  text ".Layer_Name" at 577,-858.49 h60
M5 Assembly Top:
  lines w10: -292,-930.17 6308,-930.17 ; -292,-726.83 6310,-726.83 ; -292,-523.5 -292,-1133.5 3713,-1133.5 6310,-1133.5 6310,-523.5 -291.5,-523.5 -291.5,-1133.5 1284,-1133.5 ; 2173,-1133.5 2173,-523.5 ; 3440,-726.83 3440,-523.5 ; 4280,-726.83 4280,-523.5 ; 4902,-1140 4902,-937.17
  text "COMPONENTS MARKED 'DNP' SHOULD NOT BE POPULATED." at 1153.5,-318.5 h60
  text "ASSEMBLY VARIANT:" at 1153,-434 h60
  text ".VariantName" at 2189,-434 h60
  text "PCB VIEWED FROM TOP SIDE" at -228.5,-655.67 h60
  text "BOARD #:" at 2248,-655.67 h60
  text ".PRJ_Number" at 2793.5,-655.67 h60
  text "REV:" at 3638,-655.67 h60
  text ".PCB_Rev" at 3929.5,-655.67 h60
  text "SVN REV:" at 4476,-655.67 h60
  text ".VersionControl_RevNumber" at 4982,-655.67 h60
  text "TID #:" at 2248,-859 h60
  text ".TID" at 2793.5,-859 h60
  text "PLOT NAME =" at -228.5,-1064.34 h60
  text ".plot_File_Name" at 577,-1064.34 h60
  text "GENERATED    :" at 2250,-1064.34 h60
  text ".Print_Date" at 3119.5,-1064.34 h60
  text ".Print_Time" at 3848.5,-1064.34 h60
  text "TEXAS INSTRUMENTS" at 5113,-1064.34 h60
M6 Assembly Bottom:
  lines w10: -292.5,-727.33 6309.5,-727.33 ; -290.5,-930.67 6309.5,-930.67 ; 1115.5,-1140.5 1115.5,-937.67 ; 1737.5,-727.33 1737.5,-524 ; 2577.5,-727.33 2577.5,-524 ; 3844.5,-1134 3844.5,-524 ; 4733.5,-1134 6309,-1134 6309,-524 -292.5,-524 -292.5,-1134 2304.5,-1134 6309.5,-1134 6309.5,-524
  text "COMPONENTS MARKED 'DNP' SHOULD NOT BE POPULATED." at 6102,-318 h60
  text ".VariantName" at 5058,-434 h60
  text "ASSEMBLY VARIANT:" at 6097,-434 h60
  text ".VersionControl_RevNumber" at 1035.5,-656.17 h60
  text "SVN REV:" at 1541.5,-656.17 h60
  text ".PCB_Rev" at 2088,-656.17 h60
  text "REV:" at 2379.5,-656.17 h60
  text ".PRJ_Number" at 3224,-656.17 h60
  text "BOARD #:" at 3769.5,-656.17 h60
  text "PCB VIEWED FROM BOTTOM SIDE" at 6246,-656.17 h60
  text ".TID" at 3224,-859.5 h60
  text "TID #:" at 3769.5,-859.5 h60
  text "TEXAS INSTRUMENTS" at 904.5,-1064.84 h60
  text ".Print_Time" at 2169,-1064.84 h60
  text ".Print_Date" at 2898,-1064.84 h60
  text "GENERATED    :" at 3767.5,-1064.84 h60
  text ".plot_File_Name" at 5440.5,-1064.84 h60
  text "PLOT NAME =" at 6246,-1064.84 h60
M9 Title Sheet:
  drawing of 57 lines, arcs and shapes, not listed
  text "1" at 739.84,8036.5 h70
  text "2" at 3235.5,8036.5 h70
  text "3" at 5724.84,8036.5 h70
  text "4" at 8231.51,8036.5 h70
  text "5" at 10730.5,8036.5 h70
  text "6" at 13235.5,8036.5 h70
  text "A" at -416.5,6893.5 h70
  text "A" at 14383.5,6893.5 h70
  text "B" at -416.5,4513.5 h70
  text "B" at 14383.5,4513.5 h70
  text "C" at -416.5,2138.5 h70
  text "C" at 14383.5,2138.5 h70
  text "PROJECT TITLE:" at 11343.5,277.5 h45
  text ".PRJ_Title" at 11393.5,144.17 h70
  text "DESIGNED FOR:" at 11343.5,-23.5 h45
  text ".PRJ_Customer" at 11393.5,-163.5 h70
  text "D" at -416.5,-231.5 h70
  text "D" at 14383.5,-231.5 h70
  text "FILE NAME:" at 11343.5,-323.5 h45
  text ".PCB_File_Name_No_Path" at 11393.5,-443.5 h70
  text "Texas Instruments (TI) and/or its licensors do not warrant the accuracy or completeness of this specification" at 6374,-605.34 h45
  text "ENGINEER:" at 11343.5,-613.5 h45
  text "LAYOUT BY:" at 12848.5,-613.5 h45
  text "or any information contained therein. TI and/or its licensors do not warrant that this design will meet" at 6329.01,-718 h45
  text ".PRJ_Engineer" at 11393.5,-768.49 h70
  text ".PCB_Layout" at 12899,-768.49 h70
  text "the specifications, will be suitable for your application or fit for any particular purpose, or will operate in" at 6329.01,-830.67 h45
  text ".Layer_Name" at 577,-858.49 h60
  text "ALTIUM DESIGNER VERSION:" at 12848.5,-923.5 h45
  text "an implementation. TI and/or its licensors do not warrant that the design is production worthy. You should" at 6329.01,-943.33 h45
  text "completely validate and test your design implementation to confirm the system functionality for your application." at 6374,-1056 h45
  text ".print_Scale" at 11393.5,-1056.83 h70
  text ".Application_BuildNumber" at 12899,-1056.83 h70
  text "1" at 739.84,-1263.5 h70
  text "2" at 3235.5,-1263.5 h70
  text "3" at 5724.84,-1263.5 h70
  text "4" at 8231.51,-1263.5 h70
  text "5" at 10730.5,-1263.5 h70
  text "6" at 13235.5,-1263.5 h70
M10 Fab Notes:
  drawing of 189 lines, arcs and shapes, not listed
  text "DESIGN INFORMATION" at 12382.02,6356.17 h60
  text "MIN. TRACK WIDTH:" at 11737.46,6224.05 h60
  text "8" at 12833.7,6224.05 h60
  text "MIL" at 12988.46,6224.05 h60
  text "7.874" at 12667.32,6102.36 h60
  text "MIN. CLEARANCE:" at 11737.46,6099.92 h60
  text "MIL" at 12988.46,6099.92 h60
  text "MIN. VIA PAD SIZE:" at 11737.46,5975.8 h60
  text "24" at 12803.71,5975.8 h60
  text "MIL" at 12988.46,5975.8 h60
  text "0.05mm (2MIL)" at 12432.46,5845.9 h60
  text "MINIMUM ANNULAR RING" at 11408.23,5837.67 h60
  text "EXTERNAL" at 13140.46,5837.67 h60
  text "PER" at 11608.23,5727.55 h60
  text "IPC-D-275 CLASS 2 LEVEL C" at 11828.23,5727.54 h60
  text "MIL, HOLES" at 13316.46,5627.07 h60
  text "+/-" at 12924,5618.48 h60
  text "+/-" at 13778,5618.48 h60
  text "REGISTRATION TOLERANCES:" at 11408.23,5617.42 h60
  text "METAL" at 12608,5617.42 h60
  text "5" at 13184.2,5617.42 h60
  text "3" at 14017.2,5617.42 h60
  text "MIL" at 14133.46,5617.42 h60
  text "HOLE SIZE TOLERANCE (UNLESS OTHERWISE SPECIFIED):" at 11408.23,5519.1 h60
  text "+/-" at 13778,5516.23 h60
  text "3" at 14017.2,5515.17 h60
  text "MIL" at 14133.46,5515.17 h60
  text "MATERIAL:" at 11333.46,5377.52 h60
  text "FR-4 High Tg" at 12319.9,5249 h60
  text "X" at 12175.46,5241.01 h60
  text "FR-4" at 11754.46,5236.49 h60
  text "OTHER" at 13242.46,5236.49 h60
  text "62 MIL (1.6mm) +/-10%" at 12074.56,5093.46 h60
  text "X" at 11954.46,5091.01 h60
  text "THICKNESS:" at 11408.23,5085.24 h60
  text "OTHER" at 13359.46,5085.24 h60
  text "TOLERANCE:" at 11408.23,4946.92 h60
  text "X" at 12256.46,4946.92 h60
  text "ANSI IPC-6012 TYPE 3 CLASS 2" at 12434.48,4946.92 h60
  text "OTHER +/-" at 12434.46,4802.73 h60
  text "BOW & TWIST:" at 11408.23,4657.54 h60
  text "X" at 12256.46,4657.54 h60
  text "ANSI IPC-6012 TYPE 3 CLASS 2" at 12434.48,4657.54 h60
  text "OTHER +/-" at 12434.46,4510.85 h60
  text "DRILLING:" at 11333.46,4380.23 h60
  text "NC_DRILL FILES" at 13094.46,4275.04 h60
  text "REFERENCE:" at 11408.23,4271.1 h60
  text "X" at 12065.46,4271.01 h60
  text "AS SHOWN" at 12243.46,4271.1 h60
  text "X" at 12966.46,4271.1 h60
  text "OTHER" at 13392.46,4128.85 h60
  text "PTH COPPER THICKNESS:" at 11407.91,4125.32 h60
  text "X" at 12547.14,4125.32 h60
  text "20-30 um" at 12675.14,4125.32 h60
  text "BOARD FINISH:" at 11333.46,3977.73 h60
  text "SILKSCREEN:" at 11488.68,3867.6 h60
  text "X" at 12446.46,3867.6 h60
  text "TOP" at 12563.46,3867.6 h60
  text "X" at 12956.46,3867.6 h60
  text "BOTTOM" at 13074.46,3867.6 h60
  text "SILKSCREEN COLOR:" at 11488.68,3712.41 h60
  text "X" at 12445.46,3712.41 h60
  text "WHITE" at 12563.46,3712.41 h60
  text "OTHER" at 13074.46,3712.41 h60
  text "X" at 12576.46,3568.96 h60
  text "GREEN" at 12694.46,3568.96 h60
  text "OTHER" at 13312.46,3568.96 h60
  text "SOLDER RESIST COLOR:" at 11488.68,3562.1 h60
  text "X" at 12576.46,3414.71 h60
  text "MATTE" at 12694.46,3414.71 h60
  text "SEMI-GLOSS" at 13312,3414.07 h60
  text "IMMERSION GOLD (ENIG)" at 12394.46,3241.94 h60
  text "ENEPIG" at 13732,3234.72 h60
  text "SURFACE FINISH:" at 11333.46,3233.72 h60
  text "X" at 12216.46,3233.72 h60
  text "IMM. TIN/SILVER OR EQUIV" at 11663,3096.4 h60
  text "OTHER" at 13094.46,3092.47 h60
  text "ARRAY/PANEL:" at 11333.46,2937.09 h60
  text "CUT AND TRIM PER M1 BOARD OUTLINE" at 12394.46,2928.87 h60
  text "N.C. ROUTE" at 12394.46,2792.9 h60
  text "X" at 13082.46,2792.9 h60
  text "V. SCORE" at 13260.46,2792.9 h60
  text "CERTIFICATION:" at 11333.46,2663.77 h60
  text "MATERIALS AND WORKMANSHIP FOR ALL PCBS" at 12058.46,2663.77 h60
  text "TO MEET OR EXCEED THE REQUIREMENTS OF:" at 12058.46,2569.71 h60
  text "X" at 11695.97,2441.08 h60
  text "ANSI IPC-A-600F CLASS ->" at 11823.96,2441.08 h60
  text "X" at 13471.97,2441.08 h60
  text "2" at 13581.96,2441.08 h60
  text "1" at 13266.96,2439.58 h60
  text "3" at 13935.96,2439.58 h60
  text "X" at 12507.97,2293.39 h60
  text "RoHS" at 12635.96,2293.39 h60
  text "OTHER" at 13280.36,2293.39 h60
  text "PER ORDER" at 13677.42,2293.39 h60
  text "ALL BOARDS MUST MEET OR EXCEED UL94-V0 REQUIREMENTS." at 11361,2139.57 h60
  text "PCB MUST BEAR THE UL94V-0 UL REGISTERED MATERIAL ID NUMBER" at 11361,2023.5 h60
  text "ADDITIONAL REQUIREMENTS:" at 11333.46,1854.08 h60
  text "MICROSECTION:" at 11408.23,1746.95 h60
  text "YES" at 12313.96,1746.95 h60
  text "REQUIRED" at 13175.46,1602.62 h60
  text "BARE BOARD ELEC. TEST:" at 11408.23,1599.76 h60
  text "NONE" at 12713.96,1599.76 h60
  text "X" at 13057.46,1599.76 h60
  text "PER ORDER" at 13767.46,1599.76 h60
  text "XX MIL VIAS REQUIRE NON-CONDUCTIVE FILL AND PLANARIZE" at 11576.38,1394.82 h59
  text "XX MIL VIAS REQUIRE CONDUCTIVE FILL AND PLANARIZE" at 11584.38,1290.84 h60
  text "OUTER XX MIL TRACES REQUIRE 50 OHM SINGLE-ENDED IMPEDANCE" at 11583.39,1127.46 h58
  text "LAYER 2 & 3 (INNER LAYERS) XX MIL WIDE, XX MIL SPACE / TRACES REQUIRE 100 OHM DIFFERENTIAL IMPEDANCE" at 11575.39,891.74 h60
  text ".Layer_Name" at 577,-858.49 h60
M11 Gerber Information:
  lines w10: -292,-930.17 6308,-930.17 ; -292,-726.83 6310,-726.83 ; -292,-523.5 -292,-1133.5 3713,-1133.5 6310,-1133.5 6310,-523.5 -291.5,-523.5 -291.5,-1133.5 1284,-1133.5 ; 2173,-1133.5 2173,-523.5 ; 3440,-726.83 3440,-523.5 ; 4280,-726.83 4280,-523.5 ; 4902,-1140 4902,-937.17
  text "ALL ARTWORK VIEWED FROM TOP SIDE" at -228.5,-655.67 h60
  text "BOARD #:" at 2248,-655.67 h60
  text ".PRJ_Number" at 2793.5,-655.67 h60
  text "REV:" at 3638,-655.67 h60
  text ".PCB_Rev" at 3929.5,-655.67 h60
  text "SVN REV:" at 4476,-655.67 h60
  text ".VersionControl_RevNumber" at 4982,-655.67 h60
  text "LAYER NAME =" at -228.5,-858.49 h60
  text "TID #:" at 2248,-859 h60
  text ".TID" at 2793.5,-859 h60
  text "PLOT NAME =" at -228.5,-1064.34 h60
  text ".plot_File_Name" at 577,-1064.34 h60
  text "GENERATED    :" at 2250,-1064.34 h60
  text ".Print_Date" at 3119.5,-1064.34 h60
  text ".Print_Time" at 3848.5,-1064.34 h60
  text "TEXAS INSTRUMENTS" at 5113,-1064.34 h60
M12 Stackup:
  drawing of 191 lines, arcs and shapes, not listed
  text "Layer" at 9821.59,7874.94 h60
  text "Name" at 10231.51,7874.94 h60
  text "Material" at 11161.25,7874.94 h60
  text "Thickness" at 12021.02,7874.94 h60
  text "Constant" at 12670.85,7874.94 h60
  text "Board Layer Stack" at 13240.71,7874.94 h60
  text "Top Overlay" at 10231.51,7754.94 h60
  text "Top Solder" at 10231.51,7634.94 h60
  text "Solder Resist" at 11161.25,7634.94 h60
  text "0.40mil" at 12021.02,7634.94 h60
  text "3.5" at 12670.85,7634.94 h60
  text "1" at 9821.59,7514.94 h60
  text "Top Layer" at 10231.51,7514.94 h60
  text "1.40mil" at 12021.02,7514.94 h60
  text "Dielectric1" at 10231.51,7394.94 h60
  text "FR-4 High Tg" at 11161.25,7394.94 h60
  text "59.20mil" at 12021.02,7394.94 h60
  text "4.8" at 12670.85,7394.94 h60
  text "2" at 9821.59,7274.94 h60
  text "Bottom Layer" at 10231.51,7274.94 h60
  text "1.40mil" at 12021.02,7274.94 h60
  text "Bottom Solder" at 10231.51,7154.94 h60
  text "Solder Resist" at 11161.25,7154.94 h60
  text "0.40mil" at 12021.02,7154.94 h60
  text "3.5" at 12670.85,7154.94 h60
  text "Bottom Overlay" at 10231.51,7034.94 h60
  text ".Layer_Name" at 577,-858.49 h60
M13 Component Bodies Top:
  text ".Layer_Name" at 577,-858.49 h60
M14 Component Bodies Bottom:
  text ".Layer_Name" at 577,-858.49 h60
M15 Courtyards Top:
  text ".Layer_Name" at 577,-858.49 h60
M16 Courtyards Bottom:
  text ".Layer_Name" at 577,-858.49 h60
Drill Drawing:
  lines w10: 5336.16,2515.35 5391.49,2515.35 5391.49,2570.68 5336.16,2570.68 5336.16,2515.35 ; 5336.16,2695.18 5391.49,2695.18 5363.82,2639.85 5336.16,2695.18 ; 5336.16,2778.18 5349.99,2778.18 5363.82,2764.35 5377.66,2778.18 5391.49,2778.18 5377.66,2792.02 5391.49,2805.85 5377.66,2805.85 5363.82,2819.68 5349.99,2805.85 5336.16,2805.85 5349.99,2792.02 5336.16,2778.18 ; 5336.16,2888.85 5391.49,2888.85 5391.49,2944.18 5336.16,2944.18 5336.16,2888.85 ; 5336.16,3041.02 5363.82,3013.35 5391.49,3041.02 5363.82,3068.68 5336.16,3041.02 ; 5336.16,3137.85 5336.16,3151.68 5349.99,3165.52 5336.16,3179.35 5336.16,3193.18 5349.99,3193.18 5363.82,3179.35 5377.66,3193.18 5391.49,3193.18 5391.49,3179.35 5377.66,3165.52 5391.49,3151.68 5391.49,3137.85 5377.66,3137.85 5363.82,3151.68 5349.99,3137.85 5336.16,3137.85 ; 5336.16,3262.35 5363.82,3276.18 5391.49,3262.35 5377.66,3290.02 5391.49,3317.68 5363.82,3303.85 5336.16,3317.68 5349.99,3290.02 5336.16,3262.35 ; 5347.23,2899.92 5380.43,2899.92 5380.43,2933.12 5347.23,2933.12 5347.23,2899.92
  lines w12: 5286,2478 8518.19,2478 ; 5286,3349.5 8518.19,3349.5 ; 5624.01,2353.5 5624.01,3474 ; 5956.17,2353.5 5956.17,3474 ; 6592.65,2353.5 6592.65,3474 ; 6851.85,2353.5 6851.85,3474 ; 7227.09,2353.5 7227.09,3474 ; 7951.64,2353.5 7951.64,3474 ; 5286,2353.5 8518.19,2353.5 8518.19,3474 5286,3474 5286,2353.5
  text "Symbol" at 5360.7,3386.85 h72
  text "Quantity" at 5661.36,3386.85 h72
  text "Finished Hole Size" at 5993.52,3386.85 h72
  text "Plated" at 6630,3386.85 h72
  text "Hole Type" at 6889.2,3386.85 h72
  text "Drill Layer Pair" at 7264.44,3386.85 h72
  text "Hole Tolerance" at 7988.99,3386.85 h72
  text "20" at 5661.36,3262.35 h60
  text "7.87mil (0.200mm)" at 5993.52,3262.35 h60
  text "PTH" at 6630,3262.35 h60
  text "Round" at 6889.2,3262.35 h60
  text "Top Layer - Bottom Layer" at 7264.44,3262.35 h60
  text "55" at 5661.36,3137.85 h60
  text "8.00mil (0.203mm)" at 5993.52,3137.85 h60
  text "PTH" at 6630,3137.85 h60
  text "Round" at 6889.2,3137.85 h60
  text "Top Layer - Bottom Layer" at 7264.44,3137.85 h60
  text "527" at 5661.36,3013.35 h60
  text "12.00mil (0.305mm)" at 5993.52,3013.35 h60
  text "PTH" at 6630,3013.35 h60
  text "Round" at 6889.2,3013.35 h60
  text "Top Layer - Bottom Layer" at 7264.44,3013.35 h60
  text "8" at 5661.36,2888.85 h60
  text "33.47mil (0.850mm)" at 5993.52,2888.85 h60
  text "PTH" at 6630,2888.85 h60
  text "Round" at 6889.2,2888.85 h60
  text "Top Layer - Bottom Layer" at 7264.44,2888.85 h60
  text "4" at 5661.36,2764.35 h60
  text "35.00mil (0.889mm)" at 5993.52,2764.35 h60
  text "PTH" at 6630,2764.35 h60
  text "Round" at 6889.2,2764.35 h60
  text "Top Layer - Bottom Layer" at 7264.44,2764.35 h60
  text "40" at 5661.36,2639.85 h60
  text "40.16mil (1.020mm)" at 5993.52,2639.85 h60
  text "PTH" at 6630,2639.85 h60
  text "Round" at 6889.2,2639.85 h60
  text "Top Layer - Bottom Layer" at 7264.44,2639.85 h60
  text "8" at 5661.36,2515.35 h60
  text "45.28mil (1.150mm)" at 5993.52,2515.35 h60
  text "PTH" at 6630,2515.35 h60
  text "Round" at 6889.2,2515.35 h60
  text "Top Layer - Bottom Layer" at 7264.44,2515.35 h60
  text "662 Total" at 5661.36,2390.85 h60
  text ".Layer_Name" at 577,-858.49 h60
M17 Embedded Cavity:
  text ".Layer_Name" at 577,-858.49 h60
M18 Embedded Assembly:
  text ".Layer_Name" at 577,-858.49 h60
M19 Embedded Keepout:
  text ".Layer_Name" at 577,-858.49 h60

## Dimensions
0,0 to 0,2362.2 on M2 Board Dimensions
0,-400 to 1000,-400 on M2 Board Dimensions
0,0 to 3937.01,0 on M2 Board Dimensions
